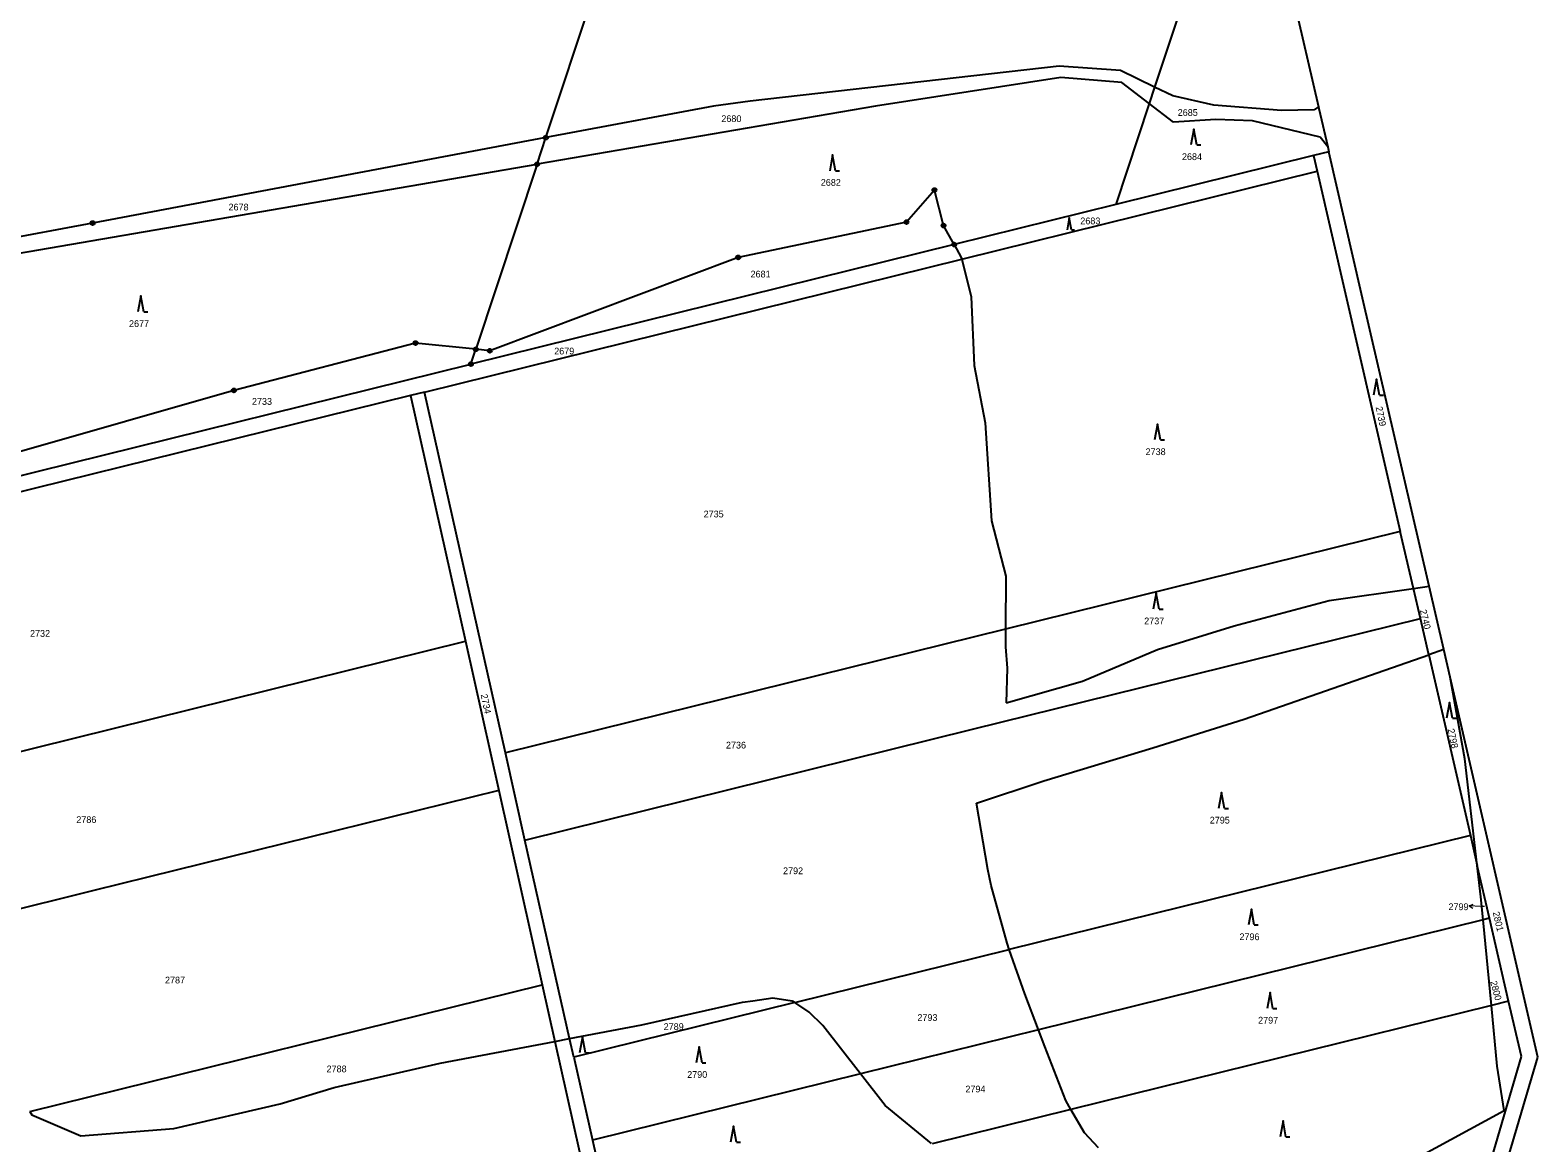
# Model space of a CAD drawing. Extents: x -606517 to -602431, y -1183120 to -1179397.
# Drawn here: x -603949.5 to -603569.1, y -1181863.9 to -1181583.1 of the extents above; entities that cross this region are included whole.
import ezdxf

# ---------------------------------------------------------------- set-up
doc = ezdxf.new("R2010")
doc.units = 0
doc.header["$LTSCALE"] = 0.68
for name, color, linetype, lineweight in [('1', 7, 'Continuous', 25), ('3', 7, 'Continuous', 25), ('7', 7, 'Continuous', 13), ('8', 7, 'Continuous', 25)]:
    doc.layers.add(name, color=color, linetype=linetype, lineweight=lineweight)
doc.layers.add('2', color=7, linetype='Continuous')

msp = doc.modelspace()

# ---------------------------------------------------------------- linework, layer by layer
at = {"layer": '1'}
for p, q in [((-603819.4, -1181610.24), (-603777.21, -1181482.74)), ((-603643.71, -1181530.76), (-603665.79, -1181597.48)), ((-603633.7, -1181562.72), (-603624.46, -1181602.46)), ((-603689.89, -1181592.17), (-603767.85, -1181601.02)), ((-603674.4, -1181593.27), (-603689.89, -1181592.17)), ((-603665.79, -1181597.48), (-603674.4, -1181593.27)), ((-603689.43, -1181595.03), (-603736.19, -1181602.28)), ((-603674.11, -1181596.34), (-603689.43, -1181595.03)), ((-603667.17, -1181601.64), (-603674.11, -1181596.34)), ((-603665.79, -1181597.48), (-603667.17, -1181601.64)), ((-603661.24, -1181599.7), (-603665.79, -1181597.48)), ((-603767.85, -1181601.02), (-603777.12, -1181602.27)), ((-603667.17, -1181601.64), (-603675.61, -1181627.14)), ((-603661, -1181606.34), (-603667.17, -1181601.64)), ((-603650.82, -1181602.01), (-603661.24, -1181599.7)), ((-603736.19, -1181602.28), (-603821.62, -1181616.95)), ((-603777.12, -1181602.27), (-603819.4, -1181610.24)), ((-603633.77, -1181603.41), (-603650.82, -1181602.01)), ((-603625.5, -1181603.27), (-603633.77, -1181603.41)), ((-603624.46, -1181602.46), (-603625.5, -1181603.27)), ((-603624.46, -1181602.46), (-603624.36, -1181602.88)), ((-603624.36, -1181602.88), (-603622.13, -1181612.55)), ((-603650.35, -1181605.69), (-603661, -1181606.34)), ((-603641.06, -1181605.99), (-603650.35, -1181605.69)), ((-603624.03, -1181610.14), (-603641.06, -1181605.99)), ((-603819.4, -1181610.24), (-603933.78, -1181631.79)), ((-603821.62, -1181616.95), (-603819.4, -1181610.24)), ((-603622.13, -1181612.55), (-603624.03, -1181610.14)), ((-603622.13, -1181612.55), (-603621.83, -1181613.83)), ((-603961.07, -1181640.89), (-603821.62, -1181616.95)), ((-603821.62, -1181616.95), (-603837.07, -1181663.65)), ((-603625.72, -1181614.79), (-603675.61, -1181627.14)), ((-603621.83, -1181613.83), (-603625.72, -1181614.79)), ((-603625.72, -1181614.79), (-603624.82, -1181618.69)), ((-603613.57, -1181649.64), (-603621.83, -1181613.83)), ((-603714.47, -1181640.88), (-603624.82, -1181618.69)), ((-603624.82, -1181618.69), (-603603.82, -1181709.63)), ((-603721.35, -1181623.46), (-603728.41, -1181631.57)), ((-603719.05, -1181632.43), (-603721.35, -1181623.46)), ((-603675.61, -1181627.14), (-603716.38, -1181637.23)), ((-603933.78, -1181631.79), (-604048.16, -1181653.34)), ((-603728.41, -1181631.57), (-603770.86, -1181640.46)), ((-603716.38, -1181637.23), (-603719.05, -1181632.43)), ((-603716.38, -1181637.23), (-603838.31, -1181667.4)), ((-603716.38, -1181637.23), (-603714.58, -1181640.45)), ((-603850.07, -1181674.43), (-603714.47, -1181640.88)), ((-603770.86, -1181640.46), (-603833.56, -1181664.02)), ((-603714.58, -1181640.45), (-603714.47, -1181640.88)), ((-603714.47, -1181640.88), (-603712.07, -1181650.43)), ((-603712.07, -1181650.43), (-603711.31, -1181667.76)), ((-603596.52, -1181723.46), (-603613.57, -1181649.64)), ((-603852.28, -1181662.07), (-603898.12, -1181674.03)), ((-603837.07, -1181663.65), (-603852.28, -1181662.07)), ((-603838.31, -1181667.4), (-603837.07, -1181663.65)), ((-603833.56, -1181664.02), (-603837.07, -1181663.65)), ((-603947.81, -1181694.5), (-603838.31, -1181667.4)), ((-603711.31, -1181667.76), (-603708.58, -1181682.2)), ((-603898.12, -1181674.03), (-603952.85, -1181689.67)), ((-603853.55, -1181675.29), (-603955.71, -1181700.57)), ((-603850.07, -1181674.43), (-603853.55, -1181675.29)), ((-603853.55, -1181675.29), (-603839.69, -1181737.33)), ((-603829.62, -1181765.5), (-603850.07, -1181674.43)), ((-603708.58, -1181682.2), (-603706.96, -1181706.9)), ((-604057.31, -1181721.59), (-603947.81, -1181694.5)), ((-603706.96, -1181706.9), (-603703.31, -1181720.9)), ((-603603.82, -1181709.63), (-603703.39, -1181734.27)), ((-603600.5, -1181724.03), (-603603.82, -1181709.63)), ((-603703.31, -1181720.9), (-603703.39, -1181734.27)), ((-603600.5, -1181724.03), (-603596.52, -1181723.46)), ((-603592.85, -1181739.39), (-603596.52, -1181723.46)), ((-603645.74, -1181733.42), (-603621.79, -1181727.07)), ((-603621.79, -1181727.07), (-603600.5, -1181724.03)), ((-603598.75, -1181731.59), (-603600.5, -1181724.03)), ((-603703.39, -1181734.27), (-603829.62, -1181765.5)), ((-603711.72, -1181759.54), (-603598.75, -1181731.59)), ((-603703.39, -1181734.27), (-603703.41, -1181738.74)), ((-603665.07, -1181739.38), (-603645.74, -1181733.42)), ((-603596.64, -1181740.72), (-603598.75, -1181731.59)), ((-603938.47, -1181761.78), (-603839.69, -1181737.33)), ((-603839.69, -1181737.33), (-603831.28, -1181774.95)), ((-603703.41, -1181738.74), (-603702.98, -1181744.09)), ((-603684.01, -1181747.37), (-603665.07, -1181739.38)), ((-603643.22, -1181757.02), (-603596.64, -1181740.72)), ((-603592.85, -1181739.39), (-603596.64, -1181740.72)), ((-603596.64, -1181740.72), (-603586.12, -1181786.33)), ((-603591.23, -1181746.38), (-603592.85, -1181739.39)), ((-603702.98, -1181744.09), (-603703.28, -1181752.85)), ((-603587.5, -1181766.99), (-603591.23, -1181746.38)), ((-603569.1, -1181842.26), (-603591.23, -1181746.38)), ((-603703.28, -1181752.85), (-603684.01, -1181747.37)), ((-603666.28, -1181764.21), (-603643.22, -1181757.02)), ((-603824.68, -1181787.49), (-603711.72, -1181759.54)), ((-604037.25, -1181786.22), (-603938.47, -1181761.78)), ((-603693.72, -1181772.54), (-603666.28, -1181764.21)), ((-603824.68, -1181787.49), (-603829.62, -1181765.5)), ((-603584.38, -1181793.87), (-603587.5, -1181766.99)), ((-603710.76, -1181778.2), (-603693.72, -1181772.54)), ((-603831.28, -1181774.95), (-603933.44, -1181800.23)), ((-603831.28, -1181774.95), (-603820.32, -1181824.01)), ((-603707.89, -1181794.9), (-603710.76, -1181778.2)), ((-603813.43, -1181837.58), (-603824.68, -1181787.49)), ((-603586.12, -1181786.33), (-603702.48, -1181815.12)), ((-603586.12, -1181786.33), (-603584.38, -1181793.87)), ((-603707.02, -1181798.98), (-603707.89, -1181794.9)), ((-603581.29, -1181807.23), (-603584.38, -1181793.87)), ((-603583.46, -1181801.78), (-603584.38, -1181793.87)), ((-603703.04, -1181813.54), (-603707.02, -1181798.98)), ((-603933.44, -1181800.23), (-604035.6, -1181825.51)), ((-603582.9, -1181807.63), (-603583.46, -1181801.78)), ((-603581.29, -1181807.23), (-603582.9, -1181807.63)), ((-603576.47, -1181828.12), (-603581.29, -1181807.23)), ((-603582.9, -1181807.63), (-603695.07, -1181835.38)), ((-603580.82, -1181829.2), (-603582.9, -1181807.63)), ((-603702.48, -1181815.12), (-603703.04, -1181813.54)), ((-603756.59, -1181828.51), (-603702.48, -1181815.12)), ((-603698.51, -1181826.29), (-603702.48, -1181815.12)), ((-603949.62, -1181856), (-603820.32, -1181824.01)), ((-603820.32, -1181824.01), (-603817.13, -1181838.29)), ((-603695.07, -1181835.38), (-603698.51, -1181826.29)), ((-603756.59, -1181828.51), (-603812.37, -1181842.31)), ((-603795.22, -1181834.1), (-603769.81, -1181828.43)), ((-603769.81, -1181828.43), (-603767.19, -1181828.05)), ((-603767.19, -1181828.05), (-603762.14, -1181827.33)), ((-603762.14, -1181827.33), (-603757.24, -1181828.08)), ((-603757.24, -1181828.08), (-603756.59, -1181828.51)), ((-603752.95, -1181830.9), (-603756.59, -1181828.51)), ((-603580.82, -1181829.2), (-603686.91, -1181855.45)), ((-603576.47, -1181828.12), (-603580.82, -1181829.2)), ((-603579.34, -1181844.52), (-603580.82, -1181829.2)), ((-603573.23, -1181842.14), (-603576.47, -1181828.12)), ((-603749.52, -1181834.32), (-603752.95, -1181830.9)), ((-603817.13, -1181838.29), (-603813.43, -1181837.58)), ((-603813.43, -1181837.58), (-603795.22, -1181834.1)), ((-603812.37, -1181842.31), (-603813.43, -1181837.58)), ((-603740.03, -1181846.5), (-603749.52, -1181834.32)), ((-603695.07, -1181835.38), (-603740.03, -1181846.5)), ((-603693.48, -1181839.59), (-603695.07, -1181835.38)), ((-603846.11, -1181843.82), (-603817.13, -1181838.29)), ((-603817.13, -1181838.29), (-603809.36, -1181873.04)), ((-603688.2, -1181853.23), (-603693.48, -1181839.59)), ((-603872.82, -1181849.92), (-603846.11, -1181843.82)), ((-603582.56, -1181873.79), (-603573.23, -1181842.14)), ((-603577.58, -1181855.74), (-603579.34, -1181844.52)), ((-603576.48, -1181867.3), (-603569.1, -1181842.26)), ((-603740.03, -1181846.5), (-603807.67, -1181863.24)), ((-603733.83, -1181854.46), (-603740.03, -1181846.5)), ((-603886.48, -1181854.03), (-603872.82, -1181849.92)), ((-603949.62, -1181856), (-603949.15, -1181856.86)), ((-603913.26, -1181860.31), (-603886.48, -1181854.03)), ((-603722.06, -1181864.07), (-603733.83, -1181854.46)), ((-603686.91, -1181855.45), (-603721.96, -1181864.12)), ((-603686.91, -1181855.45), (-603688.2, -1181853.23)), ((-603683.5, -1181861.33), (-603686.91, -1181855.45)), ((-603608.4, -1181872.48), (-603577.58, -1181855.74)), ((-603949.15, -1181856.86), (-603936.75, -1181862.09)), ((-603936.75, -1181862.09), (-603913.26, -1181860.31)), ((-603679.98, -1181865.19), (-603683.5, -1181861.33))]:
    msp.add_line(p, q, dxfattribs=at)
msp.add_lwpolyline([(-603812.37, -1181842.31), (-603807.67, -1181863.24), (-603802.97, -1181884.16)], dxfattribs=at)
at = {"layer": '3'}
for p, q in [((-603655.15, -1181612.08), (-603654.154, -1181612.08)), ((-603746.29, -1181618.58), (-603745.294, -1181618.58)), ((-603686.768, -1181633.49), (-603686.02, -1181633.49)), ((-603920.84, -1181654.19), (-603919.844, -1181654.19)), ((-603609.06, -1181675.2), (-603608.064, -1181675.2)), ((-603664.33, -1181686.52), (-603663.334, -1181686.52)), ((-603664.68, -1181729.22), (-603663.684, -1181729.22)), ((-603590.62, -1181756.76), (-603589.624, -1181756.76)), ((-603648.14, -1181779.49), (-603647.144, -1181779.49)), ((-603640.64, -1181808.92), (-603639.644, -1181808.92)), ((-603635.93, -1181829.97), (-603634.934, -1181829.97)), ((-603809.39, -1181841.14), (-603808.394, -1181841.14)), ((-603780, -1181843.67), (-603779.004, -1181843.67)), ((-603771.3, -1181863.71), (-603770.304, -1181863.71)), ((-603632.65, -1181862.36), (-603631.654, -1181862.36))]:
    msp.add_line(p, q, dxfattribs=at)
for points in [[(-603655.15, -1181612.08), (-603655.9, -1181608.08), (-603656.65, -1181612.08)], [(-603746.29, -1181618.58), (-603747.04, -1181614.58), (-603747.79, -1181618.58)], [(-603686.768, -1181633.49), (-603687.33, -1181630.49), (-603687.892, -1181633.49)], [(-603920.84, -1181654.19), (-603921.59, -1181650.19), (-603922.34, -1181654.19)], [(-603609.06, -1181675.2), (-603609.81, -1181671.2), (-603610.56, -1181675.2)], [(-603664.33, -1181686.52), (-603665.08, -1181682.52), (-603665.83, -1181686.52)], [(-603664.68, -1181729.22), (-603665.43, -1181725.22), (-603666.18, -1181729.22)], [(-603590.62, -1181756.76), (-603591.37, -1181752.76), (-603592.12, -1181756.76)], [(-603648.14, -1181779.49), (-603648.89, -1181775.49), (-603649.64, -1181779.49)], [(-603640.64, -1181808.92), (-603641.39, -1181804.92), (-603642.14, -1181808.92)], [(-603635.93, -1181829.97), (-603636.68, -1181825.97), (-603637.43, -1181829.97)], [(-603809.39, -1181841.14), (-603810.14, -1181837.14), (-603810.89, -1181841.14)], [(-603780, -1181843.67), (-603780.75, -1181839.67), (-603781.5, -1181843.67)], [(-603771.3, -1181863.71), (-603772.05, -1181859.71), (-603772.8, -1181863.71)], [(-603632.65, -1181862.36), (-603633.4, -1181858.36), (-603634.15, -1181862.36)]]:
    msp.add_lwpolyline(points, dxfattribs=at)
at = {"layer": '7'}
msp.add_line((-603586.459, -1181804.115), (-603585.476, -1181804.651), dxfattribs=at)
msp.add_lwpolyline([(-603582.53, -1181804.26), (-603583.46, -1181804.22), (-603586.459, -1181804.115), (-603585.441, -1181803.65)], dxfattribs=at)
at = {"layer": '8'}
for centre, radius in [((-603819.4, -1181610.2399), 0.5), ((-603819.4, -1181610.2399), 0.0303), ((-603821.62, -1181616.9499), 0.5), ((-603821.62, -1181616.9499), 0.0303), ((-603721.35, -1181623.4599), 0.5), ((-603721.35, -1181623.4599), 0.0303), ((-603933.78, -1181631.7899), 0.5), ((-603933.78, -1181631.7899), 0.0303), ((-603728.41, -1181631.5699), 0.5), ((-603728.41, -1181631.5699), 0.0303), ((-603719.05, -1181632.4299), 0.5), ((-603719.05, -1181632.4299), 0.0303), ((-603716.38, -1181637.2299), 0.5), ((-603716.38, -1181637.2299), 0.0303), ((-603770.86, -1181640.4599), 0.5), ((-603770.86, -1181640.4599), 0.0303), ((-603852.28, -1181662.0699), 0.5), ((-603852.28, -1181662.0699), 0.0303), ((-603837.07, -1181663.6499), 0.5), ((-603837.07, -1181663.6499), 0.0303), ((-603833.56, -1181664.0199), 0.5), ((-603833.56, -1181664.0199), 0.0303), ((-603838.31, -1181667.3999), 0.5), ((-603838.31, -1181667.3999), 0.0303), ((-603898.12, -1181674.0299), 0.5), ((-603898.12, -1181674.0299), 0.0303)]:
    msp.add_circle(centre, radius, dxfattribs=at)

# ---------------------------------------------------------------- texts
at = {"layer": '2'}
for s, p in [('2680', (-603775.13, -1181606.315)), ('2685', (-603659.97, -1181604.755)), ('2684', (-603658.9, -1181615.905)), ('2682', (-603750.04, -1181622.405)), ('2678', (-603899.48, -1181628.615)), ('2683', (-603684.55, -1181632.105)), ('2681', (-603767.76, -1181645.525)), ('2677', (-603924.59, -1181658.015)), ('2679', (-603817.3, -1181664.955)), ('2733', (-603893.57, -1181677.665)), ('2738', (-603668.08, -1181690.345)), ('2735', (-603779.6, -1181706.075)), ('2732', (-603949.57, -1181736.205)), ('2737', (-603668.43, -1181733.045)), ('2736', (-603773.96, -1181764.385)), ('2786', (-603937.89, -1181783.185)), ('2795', (-603651.89, -1181783.315)), ('2792', (-603759.56, -1181796.095)), ('2799', (-603591.65, -1181805.175)), ('2796', (-603644.39, -1181812.745)), ('2787', (-603915.51, -1181823.665)), ('2789', (-603789.68, -1181835.415)), ('2793', (-603725.66, -1181833.125)), ('2797', (-603639.68, -1181833.795)), ('2788', (-603874.74, -1181846.085)), ('2790', (-603783.75, -1181847.495)), ('2794', (-603713.55, -1181851.165))]:
    msp.add_text(s, height=1.7, dxfattribs=at).set_placement(p)
for s, rotation, p in [('2739', 282, (-603610.035, -1181678.258)), ('2740', 283, (-603598.864, -1181729.515)), ('2734', 282, (-603835.865, -1181750.828)), ('2798', 282, (-603591.865, -1181759.548)), ('2801', 283, (-603580.484, -1181805.755)), ('2800', 285, (-603581.14, -1181823.229))]:
    msp.add_text(s, height=1.7, rotation=rotation, dxfattribs=at).set_placement(p)

doc.saveas('drawing.dxf')
